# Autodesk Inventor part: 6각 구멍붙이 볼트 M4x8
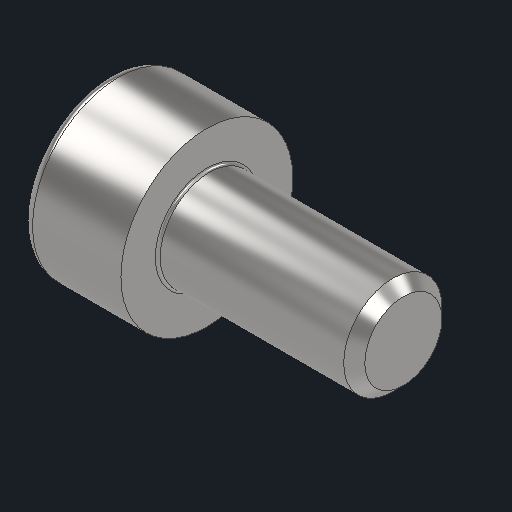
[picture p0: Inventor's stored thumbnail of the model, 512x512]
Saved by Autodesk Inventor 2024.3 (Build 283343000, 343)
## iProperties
Created: 2025-03
Part Number: 6각 구멍붙이 볼트 M4x8
Material: 강철, 연강
Description: 6각머리 태핑 나사
Document SubType Name: Modeling
Designer: user
Density: 7.85 g/cm^3
Appearance: 기본값
Author: jhkim
Sending System: Autodesk Inventor 2025
Preprocessor: ST-DEVELOPER v20
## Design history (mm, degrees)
feature "Solid1"
node "솔리드1"
